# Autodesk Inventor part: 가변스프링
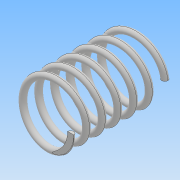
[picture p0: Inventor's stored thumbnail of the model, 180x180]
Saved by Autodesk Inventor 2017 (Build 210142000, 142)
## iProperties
Part Number: 가변스프링
Material: 일반
Document SubType Name: Modeling
Designer: user
Density: 1 g/cm^3
Appearance: 기본값
Mass: 1.05868 g
Surface Area: 21.3628 cm^2
Volume: 1.05868 cm^3
Author: user
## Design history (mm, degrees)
sketch "스케치1"
  geometry: L1 (-9, 0)-(9, 0); L2 (0, 0)-(0, 30.5); L3 (0, 30.5)-(17.575, 30.5); C1 r 1 at (9, 0); 1 further point
  constraints: 6 end point, 2 coincident, 2 horizontal, 1 centre point, 1 midpoint, 1 vertical
  dimensions: "d0" = 18 distance of L1.start L1.end; "d1" = 30.5 distance of L2.start L2.end (derived); "d2" = 2 diameter of C1
feature "코일1" sketch "스케치1" pitch "d3" = 10; turns "d5" = 6; dims "d4" = 30.5 (= d1), "d6" = 0, angle "d7" = 90 deg, angle "d8" = 90 deg, "d9" = 0, "d10" = 0
sketch "스케치2"
  geometry: L1 (-12.5, 40)-(12.5, 40); L2 (12.5, 40)-(12.5, 0); L3 (12.5, 0)-(-12.5, 0); L4 (-12.5, 0)-(-12.5, 40); 2 further points
  constraints: 8 end point, 2 parallel, 1 coincident, 1 horizontal, 1 midpoint, 1 perpendicular
  dimensions: "d11" = 40 distance of L3.end L1.start (derived); "d12" = 25 distance of L1.start L1.end
extrude "돌출1" sketch "스케치2" stored distance "d13" = 100; taper "d14" = 0 deg
node "솔리드1"
